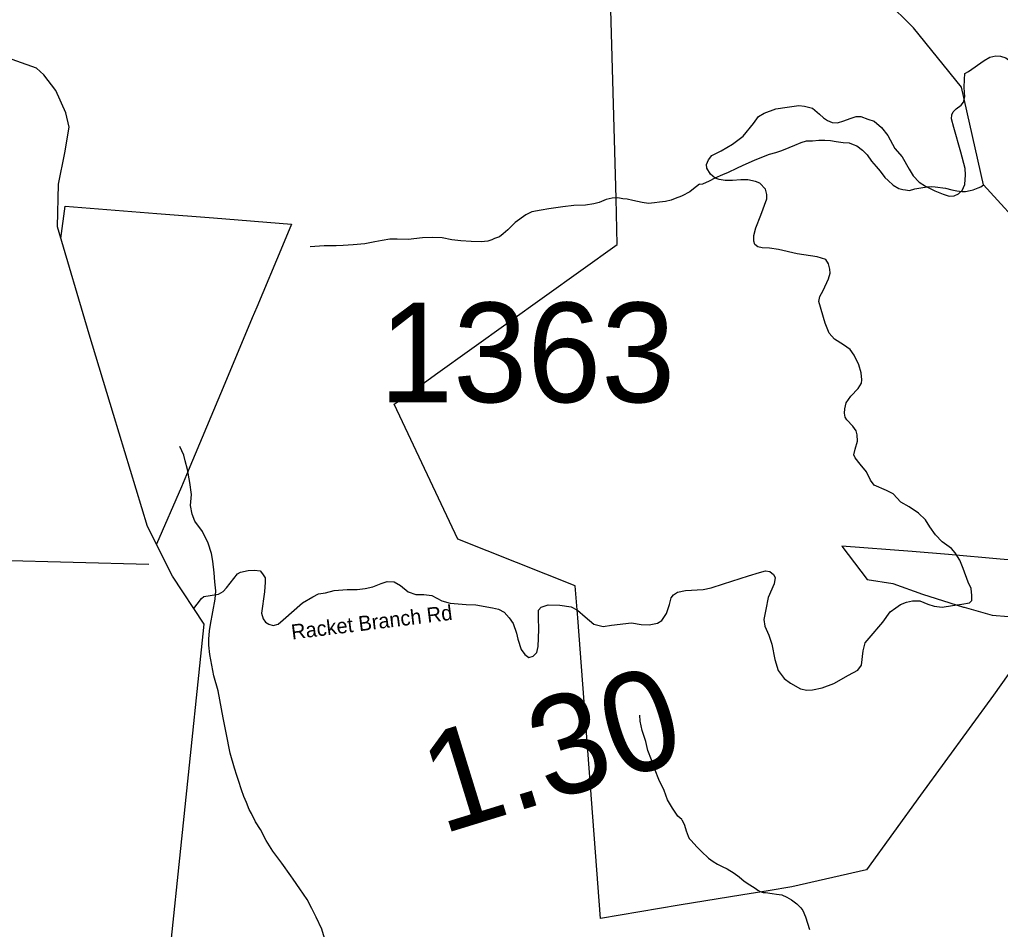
# Model space of a CAD drawing. Extents: x 1159738 to 1321356, y 736314 to 882035.
# Drawn here: x 1184188 to 1189112, y 858730 to 863298 of the extents above; entities that cross this region are included whole.
import ezdxf

# ---------------------------------------------------------------- set-up
doc = ezdxf.new("R2010")
doc.units = 0
for name, color, linetype in [('Exist Boundary Land Use Forest National US Forest Service', 7, 'Continuous'), ('Exist Boundary Political CountyLine', 7, 'Continuous'), ('Exist Hydrographic Creek Single Shore', 7, 'Continuous'), ('Exist Hydrographic Misc Water Feature', 7, 'Continuous'), ('Exist Road Non-System Type 51', 7, 'Continuous'), ('Exist Road Secondary Mileage Hundredths English Label', 7, 'Continuous'), ('Exist Road Secondary Type 41 Attributed', 7, 'Continuous'), ('Exist Road Secondary Type 51 Label', 7, 'Continuous'), ('Exist Road Secondary Type 51 Number Label', 7, 'Continuous'), ('Map Preparation Longitude Latitude Lines', 7, 'Continuous')]:
    doc.layers.add(name, color=color, linetype=linetype)

msp = doc.modelspace()

# ---------------------------------------------------------------- linework, layer by layer
at = {"layer": 'Exist Boundary Land Use Forest National US Forest Service'}
for points in [[(1189262.7, 860165.7), (1189078, 859906.6), (1188712, 859403.6), (1188440, 859029.6), (1188065, 858943.5), (1187947, 858924.3), (1187820, 858903.6), (1187500, 858851.6), (1187104.8, 858785.5), (1186990.1, 860294.2), (1186977.9, 860454.5), (1186387.9, 860688.6), (1186068.9, 861366.6), (1186103.3, 861391.2), (1186276.9, 861515.6), (1187188.9, 862168.6), (1187182.7, 862399.5), (1187157.1, 863347.4)], [(1184395.2, 862198.8), (1184416.9, 862361.5), (1184877.4, 862325.1), (1185161, 862302.6), (1185552.9, 862271.6), (1185507.1, 862162), (1185378.6, 861854.9), (1185355.7, 861800), (1185217.9, 861470.5), (1185034.2, 861032.1)], [(1185034.2, 861032.1), (1185000.9, 860952.5), (1184874.8, 860664.7)], [(1189741, 860536.5), (1189111.9, 860589.5), (1188852.2, 860611.8), (1188668.9, 860627.6), (1188315.9, 860653.5), (1188442.9, 860487.5), (1188572.9, 860466.5), (1188720.9, 860412.6), (1188927.9, 860348.6), (1188930, 860348), (1189070.9, 860308.5), (1189153.8, 860300.5)]]:
    msp.add_lwpolyline(points, dxfattribs=at)
at = {"layer": 'Exist Boundary Political CountyLine'}
msp.add_lwpolyline([(1184917.1, 858314.8), (1184924, 858427.8), (1185115.1, 860263.3), (1184955.1, 860504.1), (1184830.7, 860753), (1184658.6, 861314.7), (1184537.9, 861719.1), (1184377.9, 862257.2), (1184383.9, 862472), (1184414.3, 862629.2), (1184435.9, 862757.7), (1184420.5, 862830), (1184370, 862942.5), (1184309.5, 863020.5), (1184273.4, 863054.1), (1184098.6, 863115.7)], dxfattribs=at)
at = {"layer": 'Exist Hydrographic Creek Single Shore'}
msp.add_lwpolyline([(1191676.6, 859541.7), (1191394, 859795.3), (1191057.9, 860067.2), (1190857.9, 860389.5), (1190739.9, 860651.2), (1190719.9, 860819), (1190570.9, 861189.6), (1190271, 861471.4), (1190048, 861571), (1189815.9, 861608.6), (1189741.9, 861662.5), (1189680.9, 861863.9), (1189582.9, 861964.4), (1189329.9, 862140.2), (1189256.9, 862217.1), (1189027.1, 862468.3), (1188917.9, 862959.2), (1188675.9, 863256.1), (1188537.9, 863393.5), (1188135.8, 863631.4), (1187836.9, 864005), (1187636.9, 864169.9)], dxfattribs=at)
at = {"layer": 'Exist Hydrographic Misc Water Feature'}
for points in [[(1187601, 862471.3), (1187619, 862472.8), (1187651.5, 862488), (1187679.8, 862503.3), (1187718.4, 862520.2), (1187746.7, 862531.5), (1187789.1, 862552.2), (1187821.6, 862567.4), (1187878.3, 862591.9), (1187914.6, 862606.7), (1187952.8, 862621.7), (1187985.2, 862630.8), (1188015.4, 862640), (1188051.7, 862654.9), (1188080, 862668.2), (1188112.4, 862681.2), (1188138.5, 862688.6), (1188168.6, 862689.7), (1188200.6, 862692.9), (1188230.7, 862692), (1188258.7, 862691.3), (1188288.5, 862686.5), (1188322.4, 862681.5), (1188352.4, 862678.7), (1188374.1, 862670.2), (1188392.1, 862663.6), (1188419.5, 862642.9), (1188442.8, 862618.3), (1188466, 862587.6), (1188489.3, 862561), (1188508.6, 862536.4), (1188531.9, 862505.8), (1188549.4, 862489.3), (1188574.8, 862466.6), (1188602.4, 862449.9), (1188622.2, 862445.3), (1188636.3, 862442.9), (1188656.2, 862440.3), (1188682.4, 862447.6), (1188712.6, 862452.9), (1188744.6, 862458), (1188764.7, 862459.5), (1188784.7, 862458.9), (1188836.6, 862451.5), (1188868.4, 862442.7), (1188894.2, 862437.9), (1188920.2, 862435.2), (1188938.1, 862434.7), (1188960.4, 862440.1), (1188976.6, 862443.7), (1189000.8, 862453.1), (1189014.9, 862458.7), (1189027.1, 862468.3)], [(1187601, 862471.3), (1187572.3, 862448.1), (1187553.9, 862432.7), (1187515.3, 862413.7), (1187503.2, 862408.1), (1187487.1, 862402.5), (1187458.7, 862391.3), (1187430.4, 862384.1), (1187400.2, 862381), (1187376.1, 862377.6), (1187346, 862374.4), (1187314.1, 862379.4), (1187266.4, 862388.8), (1187238.6, 862395.5), (1187216.6, 862398.1), (1187190.8, 862402.9), (1187162.8, 862401.7), (1187132.5, 862394.5), (1187098, 862379.5), (1187071.7, 862372.3), (1187029.6, 862365.5), (1186971.5, 862365.1), (1186915.3, 862358.6), (1186881.1, 862353.6), (1186845, 862348.6), (1186806.8, 862341.7), (1186760.5, 862333), (1186730, 862317.9), (1186676.9, 862279.3), (1186639.8, 862242.4), (1186615.3, 862223.1), (1186596.7, 862207.6), (1186572.5, 862198.3), (1186558.4, 862192.6), (1186538.1, 862185.2), (1186506, 862182.1), (1186456, 862183.5), (1186404.1, 862187), (1186358.2, 862192.3), (1186310.4, 862201.7), (1186260.3, 862203.1), (1186210.4, 862202.5), (1186138.1, 862194.5), (1186084.1, 862196), (1186046, 862195.1), (1186007.7, 862188.1), (1185971.6, 862181.3), (1185921.3, 862172.7), (1185863.2, 862166.3), (1185813, 862163.6), (1185776.8, 862162.7), (1185716.9, 862162.4), (1185646.6, 862156.5)], [(1185724, 858669.6), (1185705.8, 858732.2), (1185677.4, 858791), (1185654.6, 858835.7), (1185632, 858880.4), (1185595.5, 858933.5), (1185560.8, 858982.5), (1185549.1, 858998.8), (1185505, 859062.1), (1185458.7, 859123.5), (1185426.2, 859176.4), (1185397.7, 859231.3), (1185372.8, 859270), (1185351.9, 859312.6), (1185340.6, 859333), (1185327.6, 859367.4), (1185314.2, 859397.7), (1185301.3, 859430.2), (1185286.7, 859478.6), (1185279.3, 859502.8), (1185266.2, 859539.2), (1185244.4, 859615.9), (1185225.2, 859716.5), (1185209.4, 859793), (1185185.3, 859927.8), (1185163.4, 860002.5), (1185142.4, 860111.2), (1185137.7, 860157.3), (1185138.5, 860187.3), (1185141.8, 860229.3), (1185146.6, 860261.2), (1185158.5, 860324.9), (1185170.3, 860388.6), (1185173.6, 860430.5), (1185168.7, 860474.7), (1185164, 860520.9), (1185157.7, 860579.1), (1185150.8, 860617.3), (1185134.3, 860669.8), (1185105.9, 860728.7), (1185067.2, 860779.7), (1185054.2, 860814.2), (1185045.5, 860858.5), (1185051, 860914.4), (1185042.7, 860974.6), (1185030.6, 861039), (1185019.9, 861083.3), (1185012.6, 861111.6), (1184991.8, 861154.2)], [(1187512.7, 859281.5), (1187493, 859298), (1187466.1, 859338.8), (1187441.4, 859381.6), (1187424.7, 859428.1), (1187398.3, 859482.8), (1187379.5, 859529.4), (1187361.1, 859582), (1187342.3, 859628.5), (1187331.5, 859672.9), (1187313.2, 859729.5), (1187304.6, 859775.7), (1187301.3, 859805.8)], [(1187512.7, 859281.5), (1187525.9, 859253.1), (1187535, 859224.8), (1187544.4, 859198.5), (1187550, 859186.3), (1187559.8, 859176.1), (1187589.1, 859145.3), (1187612.2, 859120.7), (1187647.3, 859087.6), (1187671, 859071), (1187692.5, 859058.3), (1187716.3, 859045.7), (1187740.1, 859035), (1187775.4, 859012), (1187800.9, 858993.4), (1187826.3, 858972.6), (1187853.7, 858953.8), (1187881.3, 858937), (1187895, 858926.6), (1187906.9, 858920.3), (1187920.6, 858916), (1187932.6, 858915.6), (1187966.5, 858910.6), (1187988.4, 858908), (1188014.3, 858903.3), (1188039.9, 858892.6), (1188063.6, 858878), (1188091, 858859.2), (1188110.4, 858838.7), (1188120.1, 858824.4), (1188133.3, 858793.9), (1188153.6, 858729.4)]]:
    msp.add_lwpolyline(points, dxfattribs=at)
at = {"layer": 'Exist Road Non-System Type 51'}
for points in [[(1188951.9, 863036.5), (1189030.9, 863092.5), (1189059.7, 863109.8), (1189089.5, 863115.4), (1189112.5, 863114), (1189139.8, 863105.3), (1189161.3, 863089.5), (1189201.6, 863052.1), (1189240.4, 863019.1), (1189289.2, 862980.2), (1189328, 862963), (1189365.4, 862952.9), (1189381.2, 862951.5), (1189415.7, 862960.1), (1189461.6, 862977.4), (1189494.7, 862994.6)], [(1188331.5, 861343.2), (1188338.9, 861373.7), (1188361.9, 861406.8), (1188399.2, 861445.6), (1188415.1, 861472.9), (1188416.5, 861488.7), (1188413.6, 861524.7), (1188402.1, 861564.9), (1188379.1, 861613.8), (1188357.6, 861641.1), (1188324.5, 861665.6), (1188280, 861694.3), (1188252.7, 861723.1), (1188232.6, 861773.4), (1188201, 861882.7), (1188205.6, 861908), (1188222.8, 861938.2), (1188250.1, 861997.1), (1188257.3, 862024.4), (1188255.9, 862044.6), (1188250.1, 862071.9), (1188235.8, 862093.5), (1188192.6, 862106.4), (1188092.1, 862122.2), (1187998.7, 862143.8), (1187952.7, 862151), (1187916.8, 862152.4), (1187893.8, 862156.7), (1187879.4, 862168.2), (1187873.7, 862185.5), (1187873.7, 862214.2), (1187885.2, 862253.1), (1187909.6, 862316.3), (1187939.7, 862397.3), (1187939.7, 862420.3), (1187932.5, 862446.2), (1187905.2, 862476.4), (1187883.7, 862485.1), (1187844.9, 862493.7), (1187809, 862493.7), (1187767.3, 862489.4), (1187729.9, 862489.4), (1187701.2, 862495.1), (1187679.6, 862502.3), (1187656.6, 862522.4), (1187638, 862551.2), (1187636.5, 862569.9), (1187646.6, 862594.3), (1187663.8, 862615.9), (1187709.8, 862638.9), (1187767.3, 862672), (1187820.5, 862712.2), (1187872.2, 862777), (1187898, 862811.5), (1187926.8, 862827.3), (1187985.7, 862850.3), (1188041.7, 862858.9), (1188100.6, 862866.1), (1188128.7, 862863.1), (1188168.9, 862853.1), (1188203.4, 862822.9), (1188223.5, 862804.2), (1188245.1, 862791.2), (1188268.1, 862781.2), (1188295.4, 862779.7), (1188325.6, 862789.8), (1188358.6, 862801.3), (1188388.8, 862811.4), (1188411.8, 862811.4), (1188446.3, 862798.4), (1188477.9, 862788.4), (1188515.2, 862756.7), (1188546.8, 862716.5), (1188582.8, 862650.3), (1188618.7, 862608.6), (1188654.6, 862546.8), (1188674.7, 862513.7), (1188704.9, 862482.1), (1188736.5, 862461.9), (1188783.9, 862437.5), (1188825.6, 862421.7), (1188855.8, 862411.6), (1188880.2, 862413), (1188901.8, 862423.1), (1188920.4, 862440.4), (1188933.4, 862470.6), (1188937.7, 862518), (1188934.8, 862551.1), (1188913.3, 862631.6), (1188878.8, 862755.3), (1188867.1, 862799.2), (1188868.5, 862819.3), (1188875.7, 862835.1), (1188890.1, 862849.5), (1188916, 862868.2), (1188927.5, 862882.6), (1188933.2, 862909.9), (1188930.3, 862957.4), (1188931.8, 862997.6), (1188934.6, 863026.4), (1188951.9, 863036.5)]]:
    msp.add_lwpolyline(points, dxfattribs=at)
at = {"layer": 'Exist Road Secondary Type 41 Attributed'}
for points in [[(1187997, 860029.8), (1188026.5, 859989.9), (1188058.1, 859966.5), (1188109.2, 859938.7), (1188140.7, 859931.1), (1188168.5, 859933.8), (1188218, 859943.1), (1188275.6, 859965.4), (1188350.1, 860006.2), (1188397.4, 860031.2), (1188415.4, 860056.3), (1188424.1, 860128.6), (1188433.3, 860168.9), (1188452.9, 860191.8), (1188521.4, 860272.3), (1188558.4, 860324.6), (1188586.7, 860345.2), (1188611.7, 860361.6), (1188641.1, 860373.5), (1188671.5, 860379), (1188708.5, 860379), (1188747.6, 860362.7), (1188780.3, 860352.9), (1188820.7, 860348.2), (1188871.9, 860356.9), (1188918.6, 860363.4), (1188957.8, 860369.9), (1188969.7, 860381.9), (1188969.7, 860405.9), (1188966.5, 860441.8), (1188950.2, 860473.3), (1188926.2, 860541.9), (1188908.8, 860583.3), (1188884.9, 860620.4), (1188866.4, 860642.2), (1188820.7, 860675.9), (1188785.9, 860711.8), (1188757.7, 860751), (1188737, 860786.9), (1188701.1, 860819.6), (1188654.3, 860851.1), (1188613, 860875.1), (1188573.6, 860917.5), (1188539.9, 860933.9), (1188477.9, 860960), (1188460.5, 860986.1), (1188439.8, 861027.5), (1188408.3, 861065.5), (1188383.3, 861097.1), (1188376.8, 861113.4), (1188383.3, 861141.7), (1188394.2, 861182), (1188393.1, 861213.7), (1188387.6, 861233.3), (1188372.4, 861257.2), (1188340.9, 861287.7), (1188332.4, 861301.3), (1188329.7, 861322.7), (1188331.5, 861343.2)], [(1185062.8, 860342), (1185078.6, 860362.6), (1185101.3, 860392.2), (1185113.5, 860402.1), (1185143.9, 860407.4), (1185185.7, 860412.7), (1185210.7, 860427.2), (1185225.9, 860445.4), (1185281.4, 860515.3), (1185296.6, 860524.5), (1185336.1, 860532.8), (1185368, 860534.4), (1185395.3, 860530.6), (1185406.7, 860516.1), (1185420.4, 860494.8), (1185421.1, 860473.5), (1185417.3, 860425.6), (1185402.9, 860318.5), (1185410.5, 860288.8), (1185422.7, 860272.8), (1185439.4, 860263), (1185461.4, 860255.4), (1185486.5, 860263), (1185510.8, 860284.3), (1185608.8, 860370.2), (1185659.7, 860399.8), (1185688.5, 860414.2), (1185723.5, 860419.6), (1185767.8, 860431), (1185832.3, 860436.3), (1185883.2, 860436.3), (1185923.5, 860441.6), (1185960.7, 860450), (1186004, 860466.7), (1186033.6, 860476.6), (1186067.8, 860475.8), (1186099.7, 860456.1), (1186139.2, 860424.9), (1186178, 860411.2), (1186217.5, 860412), (1186257, 860406.6), (1186308.6, 860379.3), (1186350.3, 860367.9), (1186430.8, 860361.8), (1186479.4, 860360.3), (1186562.4, 860344.3), (1186592.8, 860338.2), (1186620.9, 860323), (1186646, 860294.9)], [(1186646, 860294.9), (1186665.7, 860266.8), (1186682.4, 860217.4), (1186689.3, 860186.9), (1186706.9, 860134.8), (1186724.8, 860109.6), (1186744.3, 860095.7), (1186767, 860102.2), (1186784.1, 860120.9), (1186792.2, 860151), (1186795.4, 860235.6), (1186793.8, 860296.6), (1186793.8, 860333.1), (1186806, 860348.6), (1186841.8, 860360), (1186900.3, 860358.4), (1186957.1, 860350.2), (1186988.8, 860333.1), (1187027, 860299.8), (1187071.7, 860262.4), (1187117.3, 860251.4), (1187160.3, 860257.9), (1187260.3, 860269.3), (1187309, 860260.4), (1187348.8, 860258.8), (1187390.3, 860266.9), (1187412.2, 860281.5), (1187436.6, 860315.7), (1187451.2, 860362), (1187459.3, 860394.5), (1187470.7, 860410), (1187491.8, 860423), (1187531.6, 860431.1), (1187620.2, 860436.8), (1187660, 860444.9), (1187722.6, 860465.3), (1187846.9, 860505.1), (1187902.7, 860522.2), (1187933.6, 860530.3), (1187955.5, 860527.9), (1187972.6, 860512.4), (1187981.5, 860497), (1187975.8, 860465.3), (1187945.8, 860396.2), (1187934.4, 860336.8), (1187924.6, 860285.6), (1187929.5, 860253.1), (1187949.8, 860207.5), (1187965.3, 860162.8), (1187980.7, 860085.1), (1187997, 860029.8)]]:
    msp.add_lwpolyline(points, dxfattribs=at)
at = {"layer": 'Map Preparation Longitude Latitude Lines'}
msp.add_line((1177483.8, 860770), (1184837.4, 860563.1), dxfattribs=at)

# ---------------------------------------------------------------- texts
at = {"layer": 'Exist Road Secondary Mileage Hundredths English Label'}
msp.add_text('1.30', height=500, rotation=17.1149, dxfattribs=at).set_placement((1186308.2, 859206.7))
at = {"layer": 'Exist Road Secondary Type 51 Label'}
msp.add_text('Racket Branch Rd', height=75, rotation=7.0503, dxfattribs=at).set_placement((1185556.4, 860185.4))
at = {"layer": 'Exist Road Secondary Type 51 Number Label'}
msp.add_text('1363', height=500, dxfattribs=at).set_placement((1185992.6, 861377))

doc.saveas('drawing.dxf')
